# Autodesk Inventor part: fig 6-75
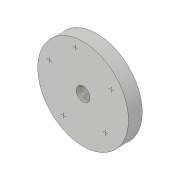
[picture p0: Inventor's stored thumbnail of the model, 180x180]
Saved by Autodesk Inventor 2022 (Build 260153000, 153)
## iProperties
Created: 2018-03
Part Number: fig 6-75
Material: Generic
Document SubType Name: Modeling
Designer: CADCIM 00
Density: 1 g/cm^3
Appearance: Default
Author: CADCIM 00
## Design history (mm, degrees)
sketch "Sketch1"
  geometry: C1 r 16.506 at (0, 0); 1 further point
  constraints: 1 centre point, 1 coincident
extrude "Extrusion1" new body sketch "Sketch1" distance "d0" = 5; taper "d1" = 0 deg
sketch "Sketch3"
  geometry: 2 further points
  constraints: 1 coincident
hole "Hole1" sketch "Sketch3" at (0, 0) diameter "d2" = 5; stored, may be unused: countersink angle "d6" = 90 deg, drill point angle "d8" = 118 deg; dims "d3" = 6, "d4" = 4, "d5" = 2, "d7" = 8
sketch "Sketch2"
  geometry: 6 further points
body "Solid1"
